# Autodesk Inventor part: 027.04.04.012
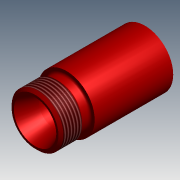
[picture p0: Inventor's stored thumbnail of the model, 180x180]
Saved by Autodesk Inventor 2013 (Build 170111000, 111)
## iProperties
Shininess: 20.0
Length Units: 11269
Angle Units: 11279
Time Units: 11290
Mass Units: 11283
Length Display Precision: 3
Angle Display Precision: 2
Created: 2001-08
Part Number: 027.04.04.012
Material: Steel, Mild
Document SubType Name: Modeling
Designer: SOleg
Density: 7.86 g/cm^3
Density: 0.0
Volumn: 0.0
Area: 0.0
PropertySet Name: Model Information
Control State: 0
Master: False
Checked Out: True
Checked Out Date: 2008-10-15
Last Check In Date: 2008-10-15
Author: SOleg
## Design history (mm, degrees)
node "WorkAxis1"
node "RevolutionFull1" dims "d4" = 360 deg
  sketch "Sketch2"
    geometry: L1 (0, 15)-(0, -35); L2 (18, 15)-(0, 15); L3 (18, -35)-(18, 15); L4 (0, -35)-(18, -35); L5 (0, 15)-(0, -35)
    constraints: 10 end point, 2 horizontal, 2 vertical, 1 other
    dimensions: "d1" = 50 distance of L3.start L2.start; "d3" = 36 diameter of L3.start L1
node "WorkPlane2"
node "WorkPlane3"
node "WorkPlane4"
node "RevolutionFull2" dims "d18" = 360 deg
node "WorkPoint2"
node "WorkPlane1"
node "RevolutionFull3" dims "d24" = 360 deg
node "Sketch7"
node "ExtrusionBlind1" dims "d39" = 5, "d40" = 0
body "Solid1"
sketch "Sketch1"
  geometry: L1 (0, -35)-(0, 15)
  constraints: 2 end point
sketch "Sketch4"
  geometry: 1 further point
node "Hole1" dims "d25" = 19, "d26" = 27, "d27" = 2, "d28" = 37 deg, "d29" = 60, "d30" = 120 deg
node "Hole2" dims "d31" = 19, "d32" = 4, "d33" = 2, "d34" = 60 deg, "d35" = 19, "d36" = 120 deg
thread "Thread1" dims "d41" = 10, "d42" = 0
sketch "Sketch3"
  geometry: L1 (0, 35)-(0, 15); L2 (14.9, 35)-(0, 35); L3 (16.5, 33.4)-(14.9, 35); L4 (16.5, 15)-(16.5, 33.4); L5 (0, 15)-(16.5, 15); L6 (0, 35)-(0, 15); C1 r 18 at (0, 15)
  constraints: 12 end point, 2 horizontal, 2 vertical, 1 centre point, 1 coincident
  dimensions: "d11" = 45 deg angle of L4 L3; "d13" = 1.6 horizontal distance of L2.start L3.start; "d15" = 20 vertical distance of L4.start L2.start; "d17" = 33 diameter of L4.start L1
sketch "Sketch5"
  geometry: L1 (15, 19.793)-(15, 16.5); L2 (16.5, 21.5)-(15.146, 20.146); L3 (16.5, 15)-(16.5, 21.5); L4 (16.5, 15)-(15, 15); L5 (15, 15)-(15, 16.5); L6 (16.5, 24.2)-(16.5, 25.2); L7 (9, 15)-(10, 15); L8 (0, 43.278)-(0, -43.278); A1 r 1.5 centre (16.5, 16.5) between (15, 16.5) and (16.5, 15); A2 r 0.5 centre (15.5, 19.793) between (15.146, 20.146) and (15, 19.793)
  constraints: 16 end point, 4 point on circle, 4 tangent, 3 vertical, 2 centre point, 2 collinear, 1 horizontal
  dimensions: "d21" = 1.5 distance of L3.start L4.end; "d23" = 6.5 distance of L3.start L2.start
sketch "Sketch6"
  geometry: C1 r 14.9 at (0, 0) reference; 1 further point
sketch "Sketch8"
  geometry: C1 r 13 at (0, -5)
  constraints: 1 centre point
  dimensions: "d38" = 26 diameter of C1
other parameters: "d2" = 36 (derived), "d5" = 0, "d6" = 0, "d7" = 0, "d8" = 0, "d9" = 0, "d10" = 45 deg (derived), "d12" = 1.6 (derived), "d16" = 33 (derived), "d19" = 0, "d20" = 1.5 (derived), "d22" = 6.5 (derived), "d37" = 26 (derived)
